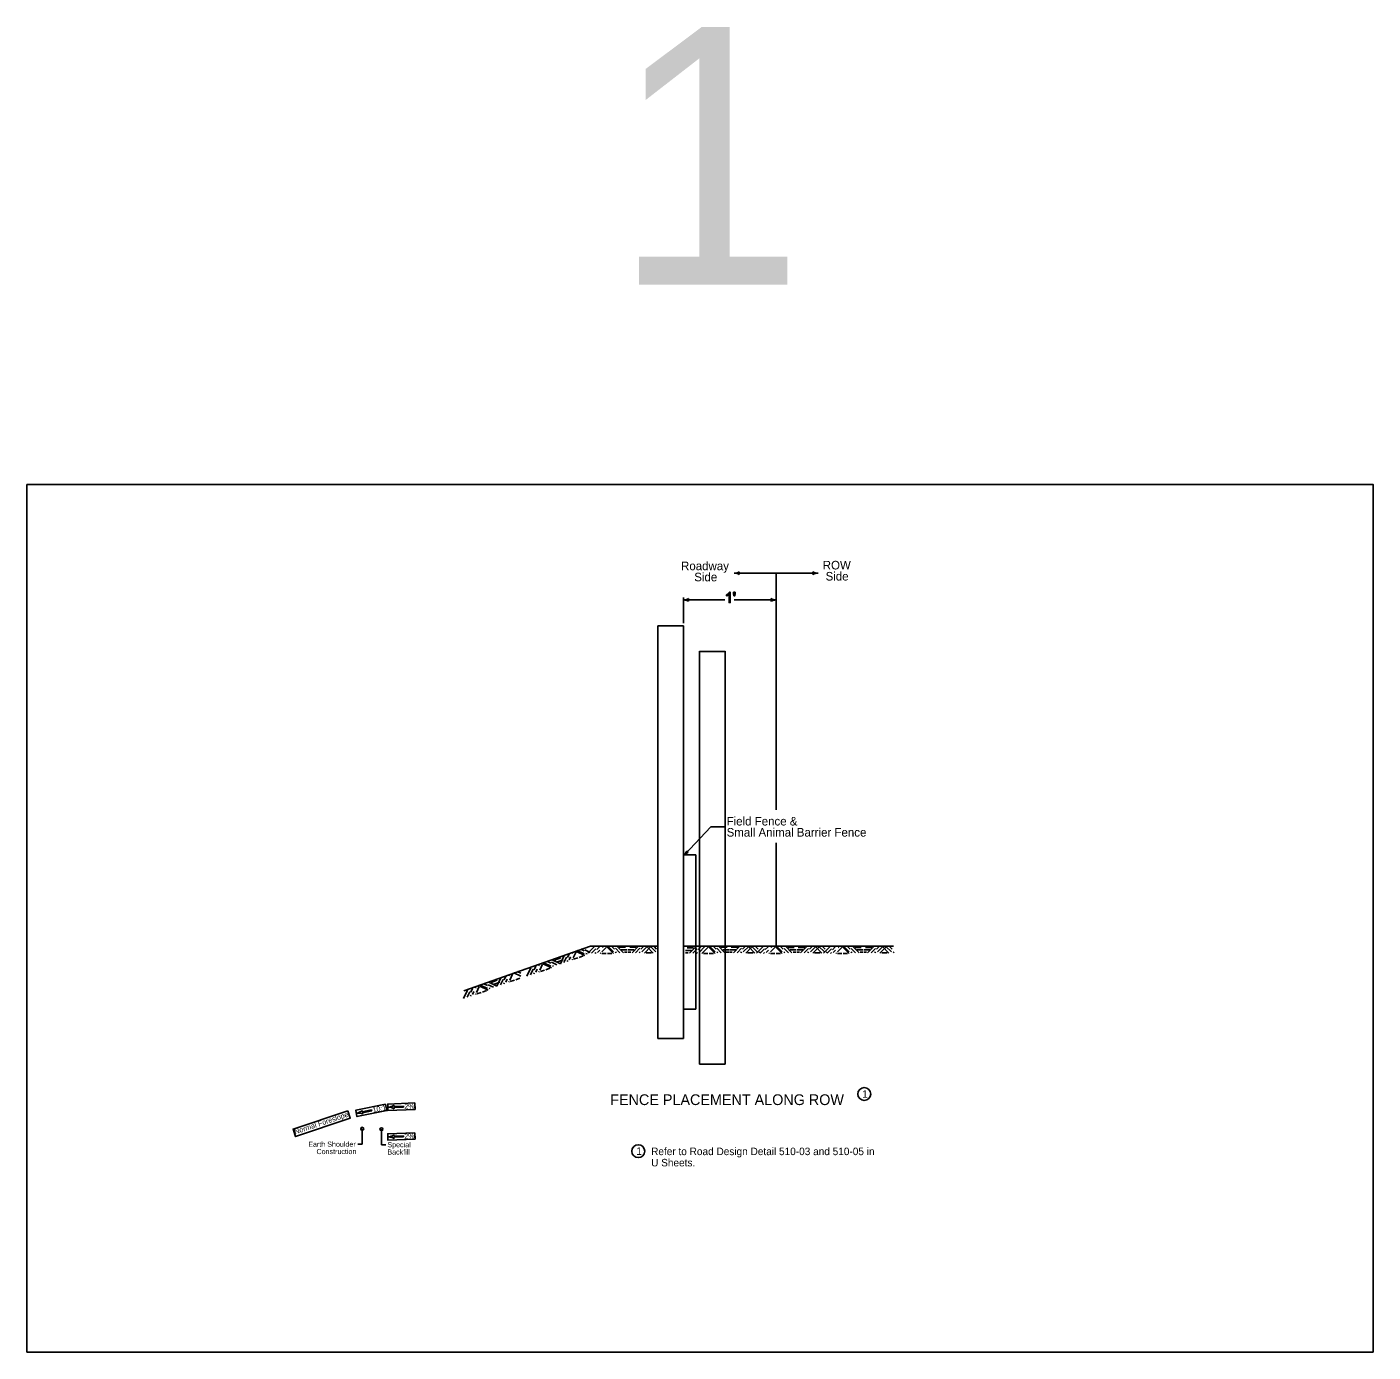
# Model space of a CAD drawing. Extents: x 10133 to 81668, y 2357 to 12713.
# Drawn here: x 10133 to 13268, y 7924 to 11009 of the extents above; entities that cross this region are included whole.
import ezdxf

# ---------------------------------------------------------------- set-up
doc = ezdxf.new("R2010")
doc.units = 0
for name, color, linetype in [('Cell', 7, 'Continuous'), ('dsnStdBlock', 7, 'Continuous'), ('dsnStdDimension', 7, 'Continuous'), ('dsnStdNote', 7, 'Continuous'), ('Level 7', 7, 'Continuous'), ('Level 8', 7, 'Continuous'), ('SheetBorder', 7, 'Continuous'), ('SheetText', 7, 'Continuous')]:
    doc.layers.add(name, color=color, linetype=linetype)

msp = doc.modelspace()

# ---------------------------------------------------------------- linework, layer by layer
at = {"layer": 'Cell'}
for p, q in [((11877.3, 9186.5), (11877.3, 9737.6)), ((11877.3, 8869.3), (11877.3, 9109.4))]:
    msp.add_line(p, q, dxfattribs=at)
at = {"layer": 'dsnStdBlock'}
for p, q in [((11698.8, 9555.4), (11698.8, 9555.5)), ((11698.8, 9555.5), (11698.8, 9532.9)), ((11758.8, 9555.4), (11698.8, 9555.4)), ((11698.8, 9532.9), (11698.8, 9532.9)), ((11698.8, 9532.9), (11698.8, 9434.6)), ((11758.8, 9532.9), (11758.8, 9555.5)), ((11758.8, 9555.5), (11758.8, 9555.4)), ((11758.8, 9434.6), (11758.8, 9532.9)), ((11758.8, 9532.9), (11758.8, 9532.9)), ((11698.8, 9434.6), (11698.8, 9434.6)), ((11698.8, 9434.6), (11698.8, 9434.6)), ((11698.8, 9434.6), (11698.8, 9081.4)), ((11758.8, 9081.4), (11758.8, 9434.6)), ((11758.8, 9434.6), (11758.8, 9434.6)), ((11758.8, 9434.6), (11758.8, 9434.6)), ((11698.8, 9081.4), (11698.8, 9081.4)), ((11698.8, 9081.4), (11698.8, 8594.3)), ((11758.8, 8594.3), (11758.8, 9081.4)), ((11758.8, 9081.4), (11758.8, 9081.4)), ((11698.8, 8594.3), (11758.8, 8594.3))]:
    msp.add_line(p, q, dxfattribs=at)
at = {"layer": 'dsnStdDimension'}
for p, q in [((11877.3, 9737.6), (11779.5, 9737.6)), ((11877.3, 9737.6), (11975.1, 9737.6)), ((11661.6, 9620.9), (11661.6, 9681.1)), ((11757.6, 9675.1), (11661.6, 9675.1)), ((11761.8, 9684.3), (11761.8, 9687.1)), ((11779.5, 9675.1), (11877.3, 9675.1)), ((11877.3, 9623.7), (11877.3, 9681.1))]:
    msp.add_line(p, q, dxfattribs=at)
msp.add_lwpolyline([(11768.7, 9693.2), (11770.6, 9693.2), (11770.6, 9669.1), (11767.7, 9669.1), (11767.7, 9687.8)], dxfattribs=at)
msp.add_lwpolyline([(11779, 9684.6), (11778.2, 9689), (11778.2, 9693.1), (11781.6, 9693.1), (11781.6, 9689), (11780.8, 9684.6)], close=True, dxfattribs=at)
for centre, radius, start, end in [((11779.5, 9763.1), 25.5, 270, 298.0725), ((11779.5, 9763.1), 25.5, 270, 298.0725), ((11779.5, 9712.1), 25.5, 61.9275, 90), ((11779.5, 9712.1), 25.5, 61.9275, 90), ((11800.9, 9737.6), 9.85, 162.2667, 197.7334), ((11800.9, 9737.6), 9.85, 162.2667, 197.7334), ((11953.8, 9737.6), 9.85, 342.2666, 17.7333), ((11975.1, 9763.1), 25.5, 241.9275, 270), ((11953.8, 9737.6), 9.85, 342.2666, 17.7333), ((11975.1, 9763.1), 25.5, 241.9275, 270), ((11975.1, 9712.1), 25.5, 90, 118.0725), ((11975.1, 9712.1), 25.5, 90, 118.0725), ((11661.6, 9700.6), 25.5, 270, 298.0725), ((11661.6, 9700.6), 25.5, 270, 298.0725), ((11661.6, 9649.6), 25.5, 61.9275, 90), ((11661.6, 9649.6), 25.5, 61.9275, 90), ((11683, 9675.1), 9.85, 162.2666, 197.7333), ((11683, 9675.1), 9.85, 162.2666, 197.7333), ((11856, 9675.1), 9.85, 342.2666, 17.7333), ((11877.3, 9700.6), 25.5, 241.9275, 270), ((11856, 9675.1), 9.85, 342.2666, 17.7333), ((11877.3, 9700.6), 25.5, 241.9275, 270), ((11877.3, 9649.6), 25.5, 90, 118.0725), ((11877.3, 9649.6), 25.5, 90, 118.0725)]:
    msp.add_arc(centre, radius, start, end, dxfattribs=at)
for points in [[(11761.8, 9687.1), (11764.2, 9688.3), (11766.1, 9689.9)], [(11767.7, 9687.8), (11766.6, 9686.8), (11764.9, 9685.8)], [(11766.1, 9689.9), (11767.9, 9691.6), (11768.7, 9693.2)], [(11764.9, 9685.8), (11763.1, 9684.8), (11761.8, 9684.3)]]:
    msp.add_open_spline(points, degree=2, dxfattribs=at)
at = {"layer": 'dsnStdNote'}
for centre in [(12082.5, 8524.8), (11556.2, 8391.7)]:
    msp.add_circle(centre, 15, dxfattribs=at)
at = {"layer": 'Level 7'}
for p, q in [((10987.1, 8498.6), (10987.2, 8495.8)), ((10987.2, 8495.8), (11009.2, 8496.6)), ((11009.2, 8496.6), (11009.3, 8494.2)), ((10901.1, 8480), (10901.1, 8480)), ((10912.9, 8486.4), (10913.4, 8483.7)), ((10913.4, 8483.7), (10935, 8488)), ((10935.4, 8485.6), (10913.9, 8481.3)), ((10913.9, 8481.3), (10914.4, 8478.6)), ((10935, 8488), (10935.4, 8485.6)), ((10974.5, 8494.1), (10974.5, 8494.1)), ((11009.3, 8494.2), (10987.3, 8493.4)), ((10987.3, 8493.4), (10987.4, 8490.6)), ((10913.4, 8407.9), (10913.4, 8443.9)), ((10958.2, 8406.8), (10958.2, 8442.8)), ((10903.4, 8407.9), (10913.4, 8407.9)), ((10968.2, 8406.8), (10958.2, 8406.8)), ((10974.5, 8424.8), (10974.5, 8424.8)), ((10987.1, 8429.4), (10987.2, 8426.6)), ((10987.2, 8426.6), (11009.2, 8427.4)), ((11009.3, 8425), (10987.3, 8424.2)), ((10987.3, 8424.2), (10987.4, 8421.4)), ((11009.2, 8427.4), (11009.3, 8425))]:
    msp.add_line(p, q, dxfattribs=at)
for points in [[(10967.8, 8501), (10898.2, 8487.1), (10901.1, 8472.4), (10970.8, 8486.3)], [(11035.9, 8504), (10972.8, 8501.5), (10973.4, 8486.5), (11036.5, 8489)], [(10879.8, 8485.9), (10752.5, 8443.2), (10758.3, 8425.8), (10885.6, 8468.5)], [(11035.9, 8434.8), (10972.8, 8432.3), (10973.4, 8417.3), (11036.5, 8419.8)]]:
    msp.add_lwpolyline(points, close=True, dxfattribs=at)
for centre in [(10913.4, 8443.9), (10958.2, 8442.8)]:
    msp.add_circle(centre, 3.5, dxfattribs=at)
for centre, start, end in [((10972.4, 8519.8), 274.6426, 304.6726), ((10895, 8505.1), 283.6619, 313.692), ((10905.1, 8454.5), 68.9279, 98.9579), ((10974.5, 8468.3), 59.9086, 89.9386), ((10972.4, 8450.6), 274.6426, 304.6726), ((10974.5, 8399.1), 59.9086, 89.9386)]:
    msp.add_arc(centre, 25.8, start, end, dxfattribs=at)
at = {"layer": 'SheetBorder'}
for p, q in [((11601.6, 9614.7), (11661.6, 9614.9)), ((11601.6, 9614.9), (11601.6, 8653.7)), ((11661.6, 8653.7), (11661.6, 9614.9)), ((11664.1, 9081.4), (11725.2, 9147)), ((11757.2, 9147), (11725.2, 9147)), ((11662.4, 9081.4), (11690, 9081.4)), ((11690, 9081.4), (11690, 8722.6)), ((11445.1, 8869.4), (11297.5, 8817.3)), ((11375.6, 8841.7), (11361.4, 8836.6)), ((11374.8, 8828.2), (11383.9, 8847.4)), ((11382.8, 8830.9), (11389, 8843.8)), ((11391.6, 8842.9), (11395.4, 8851)), ((11395.7, 8837.4), (11398.8, 8844)), ((11402.6, 8852), (11403.4, 8853.7)), ((11404.5, 8841.9), (11411.3, 8856.2)), ((11405.8, 8838.5), (11415.3, 8841.8)), ((11431.8, 8847.4), (11412.6, 8856.7)), ((11430.4, 8851), (11414.2, 8858.8)), ((11427.9, 8846.3), (11418.4, 8842.9)), ((11430.2, 8857.9), (11422.2, 8861.8)), ((11444.6, 8854), (11431.7, 8860.2)), ((11436.9, 8851.1), (11434.3, 8852.3)), ((11438.8, 8852.6), (11453.8, 8867.8)), ((11601.6, 8869.4), (11445.1, 8869.4)), ((11447.2, 8852.5), (11457.3, 8862.7)), ((11455.5, 8852.3), (11457.5, 8854.4)), ((11459.5, 8861), (11465.8, 8867.3)), ((11461.6, 8854.4), (11466.7, 8859.6)), ((11467.5, 8851.9), (11469, 8853.4)), ((11471.3, 8855.7), (11482.5, 8867)), ((11471.5, 8852.1), (11481.6, 8852.1)), ((11472.9, 8865.8), (11474.3, 8867.2)), ((11498.9, 8851.9), (11483.9, 8867)), ((11494.9, 8852.1), (11484.8, 8852.1)), ((11498.8, 8855.7), (11486.1, 8868.4)), ((11500.9, 8862.2), (11494.6, 8868.6)), ((11504.9, 8853.6), (11502.9, 8855.7)), ((11513.2, 8853.8), (11503.1, 8864)), ((11521.6, 8853.9), (11506.6, 8869)), ((11526.8, 8866.4), (11511.7, 8866.3)), ((11530.7, 8860.4), (11516.7, 8860.3)), ((11530.7, 8855.2), (11524.5, 8855.2)), ((11532.6, 8860.4), (11546.6, 8860.3)), ((11532.6, 8855.2), (11538.8, 8855.2)), ((11536.4, 8866.4), (11551.5, 8866.3)), ((11541.7, 8853.9), (11556.6, 8869)), ((11550.1, 8853.8), (11560.2, 8864)), ((11558.4, 8853.6), (11560.4, 8855.7)), ((11562.4, 8862.2), (11568.6, 8868.6)), ((11564.4, 8855.7), (11577.1, 8868.4)), ((11570.4, 8853.1), (11585.4, 8868.3)), ((11574.4, 8853.3), (11584.4, 8853.3)), ((11591.1, 8853.1), (11576.1, 8868.3)), ((11587.1, 8853.3), (11577.1, 8853.3)), ((11597.1, 8855.7), (11584.4, 8868.4)), ((11599.1, 8862.2), (11592.9, 8868.6)), ((11661.6, 8869.3), (11753.7, 8869.3)), ((11666.2, 8859.1), (11680.2, 8859)), ((11666.2, 8853.9), (11672.4, 8853.9)), ((11670, 8865.1), (11685.2, 8865)), ((11675.3, 8852.6), (11690.3, 8867.8)), ((11683.7, 8852.5), (11693.8, 8862.7)), ((11692, 8852.3), (11694, 8854.4)), ((11696, 8861), (11702.3, 8867.3)), ((11698.1, 8854.4), (11710.7, 8867.2)), ((11704, 8851.9), (11719, 8867)), ((11708, 8852.1), (11718, 8852.1)), ((11735.4, 8851.9), (11720.4, 8867)), ((11731.4, 8852.1), (11721.3, 8852.1)), ((11735.3, 8855.7), (11722.6, 8868.4)), ((11752.1, 8869.3), (11731, 8869.3)), ((11737.4, 8862.2), (11731.1, 8868.6)), ((11741.4, 8853.6), (11739.4, 8855.7)), ((11749.7, 8853.8), (11739.5, 8864)), ((11758.1, 8853.9), (11743.1, 8869)), ((11763.3, 8866.4), (11748.2, 8866.3)), ((11767.2, 8860.4), (11753.2, 8860.3)), ((11847.1, 8869.3), (11753.7, 8869.3)), ((11767.2, 8855.2), (11761, 8855.2)), ((11769.1, 8860.4), (11783.1, 8860.3)), ((11769.1, 8855.2), (11775.2, 8855.2)), ((11772.9, 8866.4), (11788, 8866.3)), ((11778.1, 8853.9), (11793.1, 8869)), ((11786.5, 8853.8), (11796.7, 8864)), ((11794.8, 8853.6), (11796.8, 8855.7)), ((11798.9, 8862.2), (11805.1, 8868.6)), ((11800.9, 8855.7), (11813.6, 8868.4)), ((11806.8, 8853.1), (11821.9, 8868.3)), ((11810.8, 8853.3), (11820.9, 8853.3)), ((11827.6, 8853.1), (11812.6, 8868.3)), ((11823.6, 8853.3), (11813.6, 8853.3)), ((11833.5, 8855.7), (11820.9, 8868.4)), ((11835.6, 8862.2), (11829.3, 8868.6)), ((11831.4, 8852.6), (11846.4, 8867.7)), ((11839.6, 8853.6), (11837.6, 8855.7)), ((11839.8, 8852.5), (11850, 8862.6)), ((11994.3, 8869.3), (11847.1, 8869.3)), ((11848.1, 8852.3), (11850.1, 8854.3)), ((11852.1, 8860.9), (11858.4, 8867.2)), ((11854.2, 8854.4), (11859.3, 8859.5)), ((11860.1, 8851.8), (11861.6, 8853.3)), ((11864, 8855.7), (11875.1, 8866.9)), ((11864.1, 8852), (11874.2, 8852)), ((11865.5, 8865.8), (11866.9, 8867.1)), ((11891.5, 8851.8), (11876.5, 8866.9)), ((11887.5, 8852), (11877.5, 8852)), ((11891.5, 8855.6), (11878.8, 8868.4)), ((11893.5, 8862.2), (11887.3, 8868.5)), ((11897.5, 8853.6), (11895.5, 8855.6)), ((11905.8, 8853.7), (11895.7, 8863.9)), ((11914.2, 8853.9), (11899.3, 8869)), ((11919.5, 8866.3), (11904.4, 8866.2)), ((11923.3, 8860.3), (11909.3, 8860.3)), ((11923.3, 8855.1), (11917.1, 8855.1)), ((11925.2, 8860.3), (11939.2, 8860.3)), ((11925.2, 8855.1), (11931.4, 8855.1)), ((11929, 8866.3), (11944.2, 8866.2)), ((11934.3, 8853.9), (11949.3, 8869)), ((11942.7, 8853.7), (11952.8, 8863.9)), ((11951, 8853.6), (11953, 8855.6)), ((11955, 8862.2), (11961.3, 8868.5)), ((11957.1, 8855.6), (11969.7, 8868.4)), ((11963, 8853.1), (11978, 8868.2)), ((11967, 8853.3), (11977, 8853.3)), ((11967, 8853.3), (11977, 8853.3)), ((11983.8, 8853.1), (11968.7, 8868.2)), ((11983.8, 8853.1), (11968.7, 8868.2)), ((11979.8, 8853.3), (11969.7, 8853.3)), ((11979.8, 8853.3), (11969.7, 8853.3)), ((11989.7, 8855.6), (11977, 8868.4)), ((11989.7, 8855.6), (11977, 8868.4)), ((11991.7, 8862.2), (11985.5, 8868.5)), ((11991.7, 8862.2), (11985.5, 8868.5)), ((11987.5, 8852.5), (12002.5, 8867.7)), ((11995.8, 8853.6), (11993.8, 8855.6)), ((12150.4, 8869.3), (11994.3, 8869.3)), ((11995.9, 8852.4), (12006.1, 8862.6)), ((12004.2, 8852.2), (12006.2, 8854.3)), ((12008.3, 8860.8), (12014.5, 8867.2)), ((12010.3, 8854.3), (12015.4, 8859.4)), ((12016.2, 8851.8), (12017.7, 8853.3)), ((12020.1, 8855.6), (12031.3, 8866.9)), ((12020.2, 8852), (12030.3, 8851.9)), ((12021.7, 8865.7), (12023, 8867)), ((12047.7, 8851.8), (12032.6, 8866.9)), ((12043.7, 8852), (12033.6, 8851.9)), ((12047.6, 8855.6), (12034.9, 8868.3)), ((12049.6, 8862.1), (12043.4, 8868.5)), ((12053.7, 8853.5), (12051.7, 8855.5)), ((12062, 8853.7), (12051.8, 8863.9)), ((12070.4, 8853.8), (12055.4, 8868.9)), ((12075.6, 8866.2), (12060.5, 8866.2)), ((12079.4, 8860.2), (12065.4, 8860.2)), ((12079.4, 8855.1), (12073.3, 8855.1)), ((12081.3, 8860.2), (12095.3, 8860.2)), ((12081.3, 8855.1), (12087.5, 8855.1)), ((12085.2, 8866.2), (12100.3, 8866.2)), ((12090.4, 8853.8), (12105.4, 8868.9)), ((12098.8, 8853.7), (12109, 8863.9)), ((12107.1, 8853.5), (12109.1, 8855.5)), ((12111.1, 8862.1), (12117.4, 8868.5)), ((12113.2, 8855.6), (12125.9, 8868.3)), ((12119.1, 8853), (12134.1, 8868.1)), ((12123.1, 8853.2), (12133.2, 8853.2)), ((12139.9, 8853), (12124.9, 8868.1)), ((12139.9, 8853), (12124.9, 8868.1)), ((12139.9, 8853), (12124.9, 8868.1)), ((12135.9, 8853.2), (12125.8, 8853.2)), ((12135.9, 8853.2), (12125.8, 8853.2)), ((12135.9, 8853.2), (12125.8, 8853.2)), ((12145.8, 8855.6), (12133.1, 8868.3)), ((12145.8, 8855.6), (12133.1, 8868.3)), ((12145.8, 8855.6), (12133.1, 8868.3)), ((12147.9, 8862.1), (12141.6, 8868.5)), ((12147.9, 8862.1), (12141.6, 8868.5)), ((12147.9, 8862.1), (12141.6, 8868.5)), ((12151.9, 8853.5), (12149.9, 8855.5)), ((11297.5, 8817.3), (11149.9, 8765.3)), ((11282.6, 8805.8), (11274.6, 8809.7)), ((11297.1, 8799.4), (11306.2, 8818.7)), ((11305.1, 8802.1), (11311.3, 8815.1)), ((11313.9, 8814.2), (11317.7, 8822.2)), ((11318, 8808.7), (11321.1, 8815.2)), ((11324.4, 8808.2), (11325.4, 8810.2)), ((11324.9, 8823.2), (11325.7, 8824.9)), ((11326.8, 8813.2), (11333.6, 8827.5)), ((11328.2, 8809.8), (11337.7, 8813.1)), ((11354.1, 8818.7), (11334.9, 8828)), ((11352.7, 8822.3), (11336.5, 8830.1)), ((11350.2, 8817.5), (11340.7, 8814.2)), ((11352.5, 8829.1), (11344.5, 8833)), ((11366.9, 8825.3), (11354, 8831.5)), ((11374.8, 8828.2), (11355.7, 8837.5)), ((11359.2, 8822.3), (11356.6, 8823.6)), ((11381.2, 8837.3), (11368, 8832.6)), ((11390.7, 8833.4), (11391.9, 8836)), ((11402.1, 8837), (11403, 8838.9)), ((11204.9, 8777.1), (11196.9, 8781)), ((11219.3, 8773.2), (11206.4, 8779.4)), ((11227.2, 8776.1), (11208.1, 8785.4)), ((11228, 8789.6), (11213.8, 8784.5)), ((11233.6, 8785.2), (11220.4, 8780.5)), ((11227.2, 8776.1), (11236.3, 8795.4)), ((11235.2, 8778.8), (11241.4, 8791.8)), ((11243.1, 8781.4), (11244.3, 8784)), ((11244, 8790.9), (11247.8, 8798.9)), ((11248.1, 8785.4), (11251.2, 8791.9)), ((11254.5, 8784.9), (11255.5, 8786.8)), ((11255, 8799.9), (11255.8, 8801.6)), ((11256.9, 8789.9), (11263.7, 8804.2)), ((11258.2, 8786.4), (11267.8, 8789.8)), ((11282.8, 8799), (11266.6, 8806.8)), ((11280.3, 8794.2), (11270.8, 8790.9)), ((11313, 8804.7), (11314.2, 8807.3)), ((11149.5, 8747.4), (11158.6, 8766.6)), ((11157.5, 8750), (11163.7, 8763)), ((11165.4, 8752.6), (11166.6, 8755.2)), ((11166.3, 8762.1), (11170.1, 8770.2)), ((11170.4, 8756.6), (11173.5, 8763.2)), ((11176.9, 8756.2), (11177.8, 8758.1)), ((11177.3, 8771.1), (11178.2, 8772.8)), ((11179.2, 8761.1), (11186, 8775.4)), ((11180.6, 8757.7), (11190.1, 8761)), ((11206.5, 8766.6), (11187.3, 8775.9)), ((11205.1, 8770.2), (11188.9, 8778)), ((11202.6, 8765.5), (11193.2, 8762.1)), ((11211.6, 8770.3), (11209, 8771.5)), ((11690, 8722.6), (11662.4, 8722.6)), ((11601.6, 8653.7), (11661.6, 8653.7))]:
    msp.add_line(p, q, dxfattribs=at)
for points in [[(10132.5, 9944), (13267.5, 9944), (13267.5, 7924), (10132.5, 7924)], [(11672.1, 9087.6), (11664.1, 9081.4), (11669.7, 9089.9)]]:
    msp.add_lwpolyline(points, close=True, dxfattribs=at)

# ---------------------------------------------------------------- texts
at = {"layer": 'dsnStdNote'}
for s, p in [('1', (12078, 8516.1)), ('1', (11551.7, 8383)), ('U Sheets.', (11586.2, 8356.3)), ('Refer to Road Design Detail 510-03 and 510-05 in', (11586.2, 8382.5))]:
    msp.add_text(s, height=17.5, dxfattribs=at).set_placement(p)
at = {"layer": 'Level 7'}
for s, rotation, p in [('10:1', 11.3093, (10938.8, 8481.4)), ('2%', 2.2909, (11011.5, 8489.5)), ('Normal Foreslope', 18.5286, (10757.5, 8430.7)), ('2%', 2.2909, (11011.5, 8420.3))]:
    msp.add_text(s, height=12, rotation=rotation, dxfattribs=at).set_placement(p)
for s, p in [('Earth Shoulder', (10787.7, 8401.9)), ('Special', (10972, 8400.8)), ('Construction', (10806.8, 8384.9)), ('Backfill', (10972, 8383.8))]:
    msp.add_text(s, height=12, dxfattribs=at).set_placement(p)
at = {"layer": 'Level 8'}
msp.add_text('FENCE PLACEMENT ALONG ROW', height=25, dxfattribs=at).set_placement((11491, 8499.1))
at = {"layer": 'SheetBorder'}
for s, p in [('Roadway', (11655.9, 9744.3)), ('ROW', (11985.9, 9746.1)), ('Side', (11686.6, 9718.5)), ('Side', (11992.5, 9720.3)), ('Field Fence &', (11762, 9150)), ('Small Animal Barrier Fence', (11762, 9124.1))]:
    msp.add_text(s, height=20, dxfattribs=at).set_placement(p)
at = {"layer": 'SheetText'}
msp.add_text('1', height=600, dxfattribs=at).set_placement((11496.6, 10409.2))

doc.saveas('drawing.dxf')
